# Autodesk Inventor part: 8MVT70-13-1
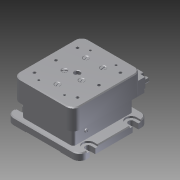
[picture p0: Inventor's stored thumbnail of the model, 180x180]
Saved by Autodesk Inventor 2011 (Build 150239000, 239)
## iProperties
Created: 2012-02
Part Number: 8MVT70-13-1
Document SubType Name: Modeling
Designer: vadybininkas6
Density: 1 g/cm^3
Author: vadybininkas6
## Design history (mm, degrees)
feature "Base1"
body "Solid1"
